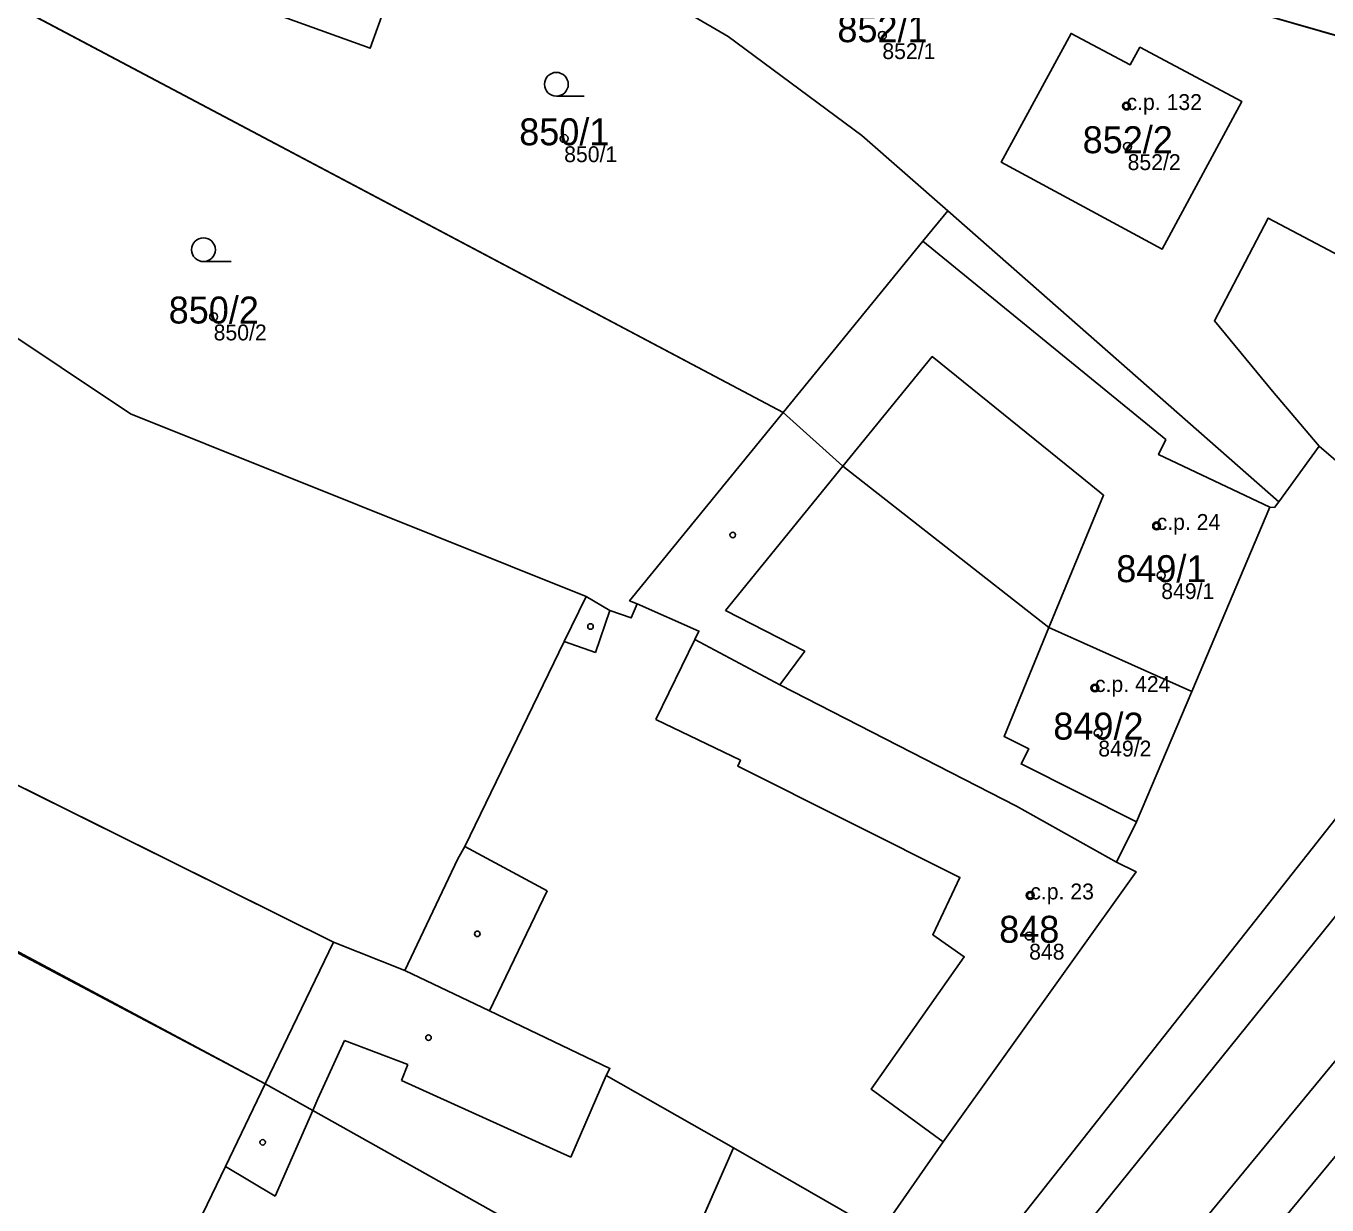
# Model space of a CAD drawing. Extents: x -603967 to -594699, y -1179315 to -1165625.
# Drawn here: x -597555.8 to -597473.7, y -1172319 to -1172244.6 of the extents above; entities that cross this region are included whole.
import ezdxf

# ---------------------------------------------------------------- set-up
doc = ezdxf.new("R2010")
doc.units = 0
for name, color, linetype in [('Definiční body', 7, 'Continuous'), ('Hranice parcel', 7, 'Continuous'), ('Parcelní čísla', 7, 'Continuous'), ('Polygon budovy', 7, 'Continuous'), ('Polygon parcely', 7, 'Continuous'), ('Vnitřní kresba', 7, 'Continuous'), ('Značky budov', 7, 'Continuous'), ('Značky kultur', 7, 'Continuous')]:
    doc.layers.add(name, color=color, linetype=linetype)

msp = doc.modelspace()

# ---------------------------------------------------------------- linework, layer by layer
at = {"layer": 'Definiční body'}
for centre in [(-597501.74, -1172245.23994), (-597486.34, -1172249.68994), (-597521.81, -1172251.73994), (-597486.27, -1172252.23994), (-597543.92, -1172262.97994), (-597484.44, -1172276.16994), (-597484.15, -1172279.28994), (-597488.33, -1172286.38994), (-597488.12, -1172289.21994), (-597492.41, -1172299.46994), (-597492.48, -1172302.02994)]:
    msp.add_circle(centre, 0.25, dxfattribs=at)
at = {"layer": 'Hranice parcel'}
for p, q in [((-597572.02, -1172235.13), (-597507.99, -1172269.01)), ((-597467.66, -1172246.81), (-597488.66, -1172240.77)), ((-597476.74, -1172274.65), (-597497.62, -1172256.3)), ((-597474.18, -1172271.14), (-597476.74, -1172274.65)), ((-597536.36, -1172302.41), (-597597.29, -1172272.16)), ((-597482.22, -1172286.6), (-597477.29, -1172274.98)), ((-597540.67, -1172311.35), (-597601.44, -1172279.22)), ((-597485.71, -1172294.82), (-597482.22, -1172286.6)), ((-597486.97, -1172297.38), (-597485.71, -1172294.82)), ((-597536.36, -1172302.41), (-597540.67, -1172311.35)), ((-597531.86, -1172304.2), (-597536.36, -1172302.41))]:
    msp.add_line(p, q, dxfattribs=at)
for points in [[(-597529.9, -1172234.54), (-597534.05, -1172246.05), (-597552.15, -1172239.51), (-597547.89, -1172228.03)], [(-597497.62, -1172256.3), (-597503.03, -1172251.55), (-597511.46, -1172245.31), (-597529.9, -1172234.54)], [(-597520.43, -1172280.62), (-597549.17, -1172269.09), (-597575.29, -1172251.66), (-597576.34, -1172253.06), (-597585.98, -1172244.84)], [(-597486.11, -1172247.1), (-597485.49, -1172245.98), (-597479.06, -1172249.41), (-597484.09, -1172258.71), (-597494.24, -1172253.22), (-597489.84, -1172245.11), (-597486.11, -1172247.1)], [(-597497.62, -1172256.3), (-597499.18, -1172258.21), (-597507.99, -1172269.01)], [(-597477.4, -1172256.76), (-597480.79, -1172263.23), (-597477.13, -1172267.67), (-597474.18, -1172271.14)], [(-597471.62, -1172259.72), (-597472.87, -1172259.15), (-597477.4, -1172256.76)], [(-597507.99, -1172269.01), (-597517.68, -1172280.89), (-597517.21, -1172281.09)], [(-597507.99, -1172269.01), (-597504.23, -1172272.41), (-597491.23, -1172282.58), (-597482.22, -1172286.6)], [(-597474.18, -1172271.14), (-597469.66, -1172275.03), (-597464.37, -1172279.02), (-597459.41, -1172273.77), (-597456.97, -1172271.01)], [(-597608.3, -1172273.28), (-597600.72, -1172277.99), (-597568.69, -1172296.39), (-597540.67, -1172311.35)], [(-597477.29, -1172274.98), (-597477.01, -1172275.01), (-597476.74, -1172274.65)], [(-597531.86, -1172304.2), (-597528.52, -1172297.17), (-597528.07, -1172296.38), (-597521.81, -1172283.46), (-597520.43, -1172280.62)], [(-597517.21, -1172281.09), (-597517.58, -1172281.97), (-597518.92, -1172281.51), (-597520.43, -1172280.62)], [(-597486.97, -1172297.38), (-597493.28, -1172293.85), (-597508.2, -1172286.2), (-597513.57, -1172283.34), (-597513.31, -1172282.8), (-597517.21, -1172281.09)], [(-597603.32, -1172338.5), (-597559.28, -1172345.76), (-597534.75, -1172348.6), (-597527.43, -1172348.17), (-597522.01, -1172347.22), (-597516.92, -1172345.77), (-597512.23, -1172343.6), (-597509.21, -1172340.34), (-597465.05, -1172284.36)], [(-597454.04, -1172292.81), (-597498.46, -1172346.48), (-597502.19, -1172353.11)], [(-597502.39, -1172320.4), (-597501.89, -1172320.74), (-597497.9, -1172315.01), (-597485.74, -1172297.98), (-597486.97, -1172297.38)], [(-597502.39, -1172320.4), (-597511.14, -1172315.38), (-597519.17, -1172310.82), (-597518.92, -1172310.38), (-597526.51, -1172306.74), (-597531.86, -1172304.2)], [(-597540.67, -1172311.35), (-597543.18, -1172316.56), (-597548.37, -1172327.32), (-597548.82, -1172327.17), (-597549.4, -1172328.69)], [(-597508.09, -1172330.01), (-597515.55, -1172325.43), (-597537.67, -1172313.03), (-597540.67, -1172311.35)]]:
    msp.add_lwpolyline(points, dxfattribs=at)
at = {"layer": 'Polygon budovy'}
for points in [[(-597552.15, -1172239.51), (-597534.05, -1172246.05), (-597529.9, -1172234.54), (-597533.28, -1172233.32), (-597547.89, -1172228.03)], [(-597494.24, -1172253.22), (-597484.09, -1172258.71), (-597479.06, -1172249.41), (-597485.49, -1172245.98), (-597486.11, -1172247.1), (-597489.84, -1172245.11)], [(-597507.99, -1172269.01), (-597504.23, -1172272.41), (-597498.59, -1172265.49), (-597489.16, -1172273.12), (-597487.79, -1172274.23), (-597491.23, -1172282.58), (-597482.22, -1172286.6), (-597477.29, -1172274.98), (-597484.32, -1172271.67), (-597483.87, -1172270.72), (-597499.18, -1172258.21)], [(-597491.23, -1172282.58), (-597494.06, -1172289.45), (-597492.51, -1172290.22), (-597492.99, -1172291.18), (-597485.71, -1172294.82), (-597482.22, -1172286.6)], [(-597516.02, -1172288.38), (-597510.69, -1172290.95), (-597510.86, -1172291.31), (-597496.85, -1172298.33), (-597498.56, -1172301.95), (-597496.58, -1172303.34), (-597502.45, -1172311.68), (-597497.9, -1172315.01), (-597485.74, -1172297.98), (-597486.97, -1172297.38), (-597493.28, -1172293.85), (-597508.2, -1172286.2), (-597513.57, -1172283.34)], [(-597515.55, -1172325.43), (-597508.09, -1172330.01), (-597502.39, -1172320.4), (-597511.14, -1172315.38)]]:
    msp.add_lwpolyline(points, close=True, dxfattribs=at)
at = {"layer": 'Polygon parcely'}
for points in [[(-597591.42, -1172351.56), (-597523.81, -1172359.42), (-597520.82, -1172360.39), (-597519.02, -1172360.12), (-597508.72, -1172358.64), (-597503.65, -1172355.71), (-597502.19, -1172353.11), (-597498.46, -1172346.48), (-597454.04, -1172292.81), (-597427.14, -1172259.05), (-597397.14, -1172220.36), (-597394.37, -1172218.5), (-597389.04, -1172216.48), (-597385.49, -1172215.44), (-597284.94, -1172206.98), (-597176.28, -1172194.43), (-597149.06, -1172188.37), (-597103.95, -1172176.52), (-597093.36, -1172173.46), (-597048.28, -1172157.97), (-597028.02, -1172148.91), (-597019.27, -1172145.73)], [(-597355.41, -1172201.88), (-597393.45, -1172204.72), (-597396.09, -1172205.78), (-597408.48, -1172210.78), (-597412.39, -1172212.36), (-597437.84, -1172252.08), (-597465.05, -1172284.36), (-597509.21, -1172340.34), (-597512.23, -1172343.6), (-597516.92, -1172345.77), (-597522.01, -1172347.22), (-597527.43, -1172348.17), (-597534.75, -1172348.6), (-597559.28, -1172345.76)], [(-597559.28, -1172345.76), (-597534.75, -1172348.6), (-597527.43, -1172348.17), (-597522.01, -1172347.22), (-597516.92, -1172345.77), (-597512.23, -1172343.6), (-597509.21, -1172340.34), (-597465.05, -1172284.36), (-597437.84, -1172252.08), (-597412.39, -1172212.36)], [(-597397.14, -1172220.36), (-597427.14, -1172259.05), (-597454.04, -1172292.81), (-597498.46, -1172346.48), (-597502.19, -1172353.11), (-597503.65, -1172355.71), (-597506.03, -1172362.48), (-597507.16, -1172367.89), (-597512.01, -1172395.8)], [(-597567.65, -1172232.09), (-597547.89, -1172228.03), (-597533.28, -1172233.32), (-597531.57, -1172228.19), (-597491.63, -1172239.62), (-597488.66, -1172240.77), (-597467.66, -1172246.81), (-597461.46, -1172248.6), (-597459.83, -1172249.89), (-597447.7, -1172259.54), (-597440.53, -1172250.32), (-597448.71, -1172245.21), (-597451.52, -1172247.77), (-597463.11, -1172244.45), (-597474.88, -1172240.83), (-597484.45, -1172237.98), (-597490.03, -1172236.12), (-597531.66, -1172224.1), (-597535.68, -1172223.42), (-597541.32, -1172223.48), (-597549.36, -1172223.56), (-597563.94, -1172226.22)], [(-597469.66, -1172275.03), (-597474.18, -1172271.14), (-597476.74, -1172274.65), (-597477.01, -1172275.01), (-597477.29, -1172274.98), (-597482.22, -1172286.6), (-597485.71, -1172294.82), (-597486.97, -1172297.38), (-597485.74, -1172297.98), (-597497.9, -1172315.01), (-597501.89, -1172320.74), (-597502.39, -1172320.4), (-597508.09, -1172330.01), (-597513.77, -1172339.58), (-597537.96, -1172332.86), (-597538.2, -1172334.01), (-597539.61, -1172345.09), (-597541.61, -1172346.69), (-597559.08, -1172344.33)]]:
    msp.add_lwpolyline(points, dxfattribs=at)
for points in [[(-597511.46, -1172245.31), (-597529.9, -1172234.54), (-597534.05, -1172246.05), (-597552.15, -1172239.51), (-597547.89, -1172228.03), (-597567.65, -1172232.09), (-597572.02, -1172235.13), (-597507.99, -1172269.01), (-597499.18, -1172258.21), (-597497.62, -1172256.3), (-597503.03, -1172251.55)], [(-597529.9, -1172234.54), (-597533.28, -1172233.32), (-597547.89, -1172228.03), (-597552.15, -1172239.51), (-597534.05, -1172246.05)], [(-597533.28, -1172233.32), (-597529.9, -1172234.54), (-597511.46, -1172245.31), (-597503.03, -1172251.55), (-597497.62, -1172256.3), (-597476.74, -1172274.65), (-597474.18, -1172271.14), (-597477.13, -1172267.67), (-597480.79, -1172263.23), (-597477.4, -1172256.76), (-597472.87, -1172259.15), (-597471.62, -1172259.72), (-597467.66, -1172246.81), (-597488.66, -1172240.77), (-597491.63, -1172239.62), (-597531.57, -1172228.19)], [(-597585.98, -1172244.84), (-597576.34, -1172253.06), (-597575.29, -1172251.66), (-597549.17, -1172269.09), (-597520.43, -1172280.62), (-597518.92, -1172281.51), (-597517.58, -1172281.97), (-597517.21, -1172281.09), (-597517.68, -1172280.89), (-597507.99, -1172269.01), (-597572.02, -1172235.13)], [(-597549.17, -1172269.09), (-597575.29, -1172251.66), (-597576.34, -1172253.06), (-597585.98, -1172244.84), (-597599.23, -1172261.03), (-597599.56, -1172261.45), (-597604.86, -1172267.5), (-597599.69, -1172270.51), (-597597.29, -1172272.16), (-597536.36, -1172302.41), (-597531.86, -1172304.2), (-597528.52, -1172297.17), (-597528.07, -1172296.38), (-597521.81, -1172283.46), (-597520.43, -1172280.62)], [(-597486.11, -1172247.1), (-597489.84, -1172245.11), (-597494.24, -1172253.22), (-597484.09, -1172258.71), (-597479.06, -1172249.41), (-597485.49, -1172245.98)], [(-597486.11, -1172247.1), (-597485.49, -1172245.98), (-597479.06, -1172249.41), (-597484.09, -1172258.71), (-597494.24, -1172253.22), (-597489.84, -1172245.11)], [(-597499.18, -1172258.21), (-597507.99, -1172269.01), (-597504.23, -1172272.41), (-597491.23, -1172282.58), (-597482.22, -1172286.6), (-597477.29, -1172274.98), (-597477.01, -1172275.01), (-597476.74, -1172274.65), (-597497.62, -1172256.3)], [(-597464.37, -1172279.02), (-597459.41, -1172273.77), (-597456.97, -1172271.01), (-597462.8, -1172265.39), (-597465.08, -1172263.3), (-597467.02, -1172261.87), (-597468.98, -1172260.4), (-597469.26, -1172260.79), (-597471.62, -1172259.72), (-597472.87, -1172259.15), (-597477.4, -1172256.76), (-597480.79, -1172263.23), (-597477.13, -1172267.67), (-597474.18, -1172271.14), (-597469.66, -1172275.03)], [(-597485.71, -1172294.82), (-597482.22, -1172286.6), (-597491.23, -1172282.58), (-597504.23, -1172272.41), (-597507.99, -1172269.01), (-597517.68, -1172280.89), (-597517.21, -1172281.09), (-597513.31, -1172282.8), (-597513.57, -1172283.34), (-597508.2, -1172286.2), (-597493.28, -1172293.85), (-597486.97, -1172297.38)], [(-597600.72, -1172277.99), (-597568.69, -1172296.39), (-597540.67, -1172311.35), (-597536.36, -1172302.41), (-597597.29, -1172272.16), (-597599.69, -1172270.51), (-597602.51, -1172275.32), (-597607.77, -1172272.21), (-597608.3, -1172273.28)], [(-597601.44, -1172279.22), (-597540.67, -1172311.35), (-597568.69, -1172296.39), (-597600.72, -1172277.99), (-597608.3, -1172273.28), (-597609.35, -1172275.04)], [(-597604.73, -1172287.83), (-597604.88, -1172288.85), (-597596.24, -1172292.02), (-597594.34, -1172293.04), (-597583.38, -1172305.98), (-597576.38, -1172314.23), (-597571.67, -1172319.55), (-597563, -1172320.77), (-597563.35, -1172323.07), (-597549.4, -1172328.69), (-597548.82, -1172327.17), (-597548.37, -1172327.32), (-597543.18, -1172316.56), (-597540.67, -1172311.35), (-597601.44, -1172279.22), (-597605.91, -1172286.83)], [(-597518.92, -1172281.51), (-597520.43, -1172280.62), (-597521.81, -1172283.46), (-597528.07, -1172296.38), (-597528.52, -1172297.17), (-597531.86, -1172304.2), (-597526.51, -1172306.74), (-597518.92, -1172310.38), (-597519.17, -1172310.82), (-597511.14, -1172315.38), (-597502.39, -1172320.4), (-597501.89, -1172320.74), (-597497.9, -1172315.01), (-597485.74, -1172297.98), (-597486.97, -1172297.38), (-597493.28, -1172293.85), (-597508.2, -1172286.2), (-597513.57, -1172283.34), (-597513.31, -1172282.8), (-597517.21, -1172281.09), (-597517.58, -1172281.97)], [(-597511.14, -1172315.38), (-597519.17, -1172310.82), (-597518.92, -1172310.38), (-597526.51, -1172306.74), (-597531.86, -1172304.2), (-597536.36, -1172302.41), (-597540.67, -1172311.35), (-597537.67, -1172313.03), (-597515.55, -1172325.43), (-597508.09, -1172330.01), (-597502.39, -1172320.4)], [(-597513.77, -1172339.58), (-597508.09, -1172330.01), (-597515.55, -1172325.43), (-597537.67, -1172313.03), (-597540.67, -1172311.35), (-597543.18, -1172316.56), (-597548.37, -1172327.32), (-597548.82, -1172327.17), (-597549.4, -1172328.69), (-597547.8, -1172329.33), (-597548.55, -1172330.69), (-597538.2, -1172334.01), (-597537.96, -1172332.86)]]:
    msp.add_lwpolyline(points, close=True, dxfattribs=at)
at = {"layer": 'Vnitřní kresba'}
for p, q in [((-597499.18, -1172258.21), (-597483.87, -1172270.72)), ((-597504.23, -1172272.41), (-597498.59, -1172265.49)), ((-597489.16, -1172273.12), (-597498.59, -1172265.49)), ((-597483.87, -1172270.72), (-597484.32, -1172271.67)), ((-597484.32, -1172271.67), (-597477.29, -1172274.98)), ((-597511.64, -1172281.5), (-597504.23, -1172272.41)), ((-597489.16, -1172273.12), (-597487.79, -1172274.23)), ((-597487.79, -1172274.23), (-597491.23, -1172282.58)), ((-597519.84, -1172284.15), (-597518.92, -1172281.51)), ((-597511.64, -1172281.5), (-597506.63, -1172284.06)), ((-597491.23, -1172282.58), (-597494.06, -1172289.45)), ((-597521.81, -1172283.46), (-597519.84, -1172284.15)), ((-597516.02, -1172288.38), (-597513.57, -1172283.34)), ((-597506.63, -1172284.06), (-597508.2, -1172286.2)), ((-597499.9, -1172333.93), (-597461.89, -1172286.79)), ((-597510.69, -1172290.95), (-597516.02, -1172288.38)), ((-597494.06, -1172289.45), (-597492.51, -1172290.22)), ((-597497.58, -1172339.5), (-597457.13, -1172290.44)), ((-597492.51, -1172290.22), (-597492.99, -1172291.18)), ((-597510.86, -1172291.31), (-597510.69, -1172290.95)), ((-597496.85, -1172298.33), (-597510.86, -1172291.31)), ((-597492.99, -1172291.18), (-597485.71, -1172294.82)), ((-597528.07, -1172296.38), (-597522.88, -1172299.18)), ((-597496.85, -1172298.33), (-597498.56, -1172301.95)), ((-597522.88, -1172299.18), (-597526.51, -1172306.74)), ((-597498.56, -1172301.95), (-597496.58, -1172303.34)), ((-597496.58, -1172303.34), (-597502.45, -1172311.68)), ((-597535.66, -1172308.62), (-597537.35, -1172312.29)), ((-597535.66, -1172308.62), (-597531.68, -1172310.14)), ((-597531.68, -1172310.14), (-597532.07, -1172311.15)), ((-597521.38, -1172315.97), (-597532.07, -1172311.15)), ((-597519.17, -1172310.82), (-597521.38, -1172315.97)), ((-597502.45, -1172311.68), (-597497.9, -1172315.01)), ((-597537.35, -1172312.29), (-597537.67, -1172313.03)), ((-597537.67, -1172313.03), (-597540.05, -1172318.43)), ((-597515.55, -1172325.43), (-597511.14, -1172315.38)), ((-597540.05, -1172318.43), (-597543.18, -1172316.56))]:
    msp.add_line(p, q, dxfattribs=at)
at = {"layer": 'Značky budov'}
for centre in [(-597486.3468, -1172249.68916), (-597511.1768, -1172276.73916), (-597484.4468, -1172276.16916), (-597520.1468, -1172282.50916), (-597488.3368, -1172286.38916), (-597492.4168, -1172299.46916), (-597527.2868, -1172301.88916), (-597530.3668, -1172308.43916), (-597540.8268, -1172315.03916)]:
    msp.add_circle(centre, 0.175, dxfattribs=at)
at = {"layer": 'Značky kultur'}
for p, q in [((-597522.303, -1172249.07), (-597520.553, -1172249.07)), ((-597544.563, -1172259.5), (-597542.813, -1172259.5))]:
    msp.add_line(p, q, dxfattribs=at)
for centre in [(-597522.30286, -1172248.31981), (-597544.56286, -1172258.74981)]:
    msp.add_circle(centre, 0.75, dxfattribs=at)

# ---------------------------------------------------------------- texts
at = {"layer": 'Definiční body'}
for s, p in [('852/1', (-597501.74, -1172246.729)), ('c.p. 132', (-597486.34, -1172249.94)), ('850/1', (-597521.81, -1172253.229)), ('852/2', (-597486.27, -1172253.729)), ('850/2', (-597543.92, -1172264.469)), ('c.p. 24', (-597484.44, -1172276.42)), ('849/1', (-597484.15, -1172280.779)), ('c.p. 424', (-597488.33, -1172286.64)), ('849/2', (-597488.12, -1172290.709)), ('c.p. 23', (-597492.41, -1172299.72)), ('848', (-597492.48, -1172303.519))]:
    msp.add_text(s, height=0.999996, dxfattribs=at).set_placement(p)
at = {"layer": 'Parcelní čísla'}
for s, p in [('852/1', (-597504.576, -1172245.665)), ('850/1', (-597524.646, -1172252.165)), ('852/2', (-597489.106, -1172252.665)), ('850/2', (-597546.756, -1172263.405)), ('849/1', (-597486.986, -1172279.715)), ('849/2', (-597490.956, -1172289.645)), ('848', (-597494.37, -1172302.455))]:
    msp.add_text(s, height=1.699998, dxfattribs=at).set_placement(p)

doc.saveas('drawing.dxf')
